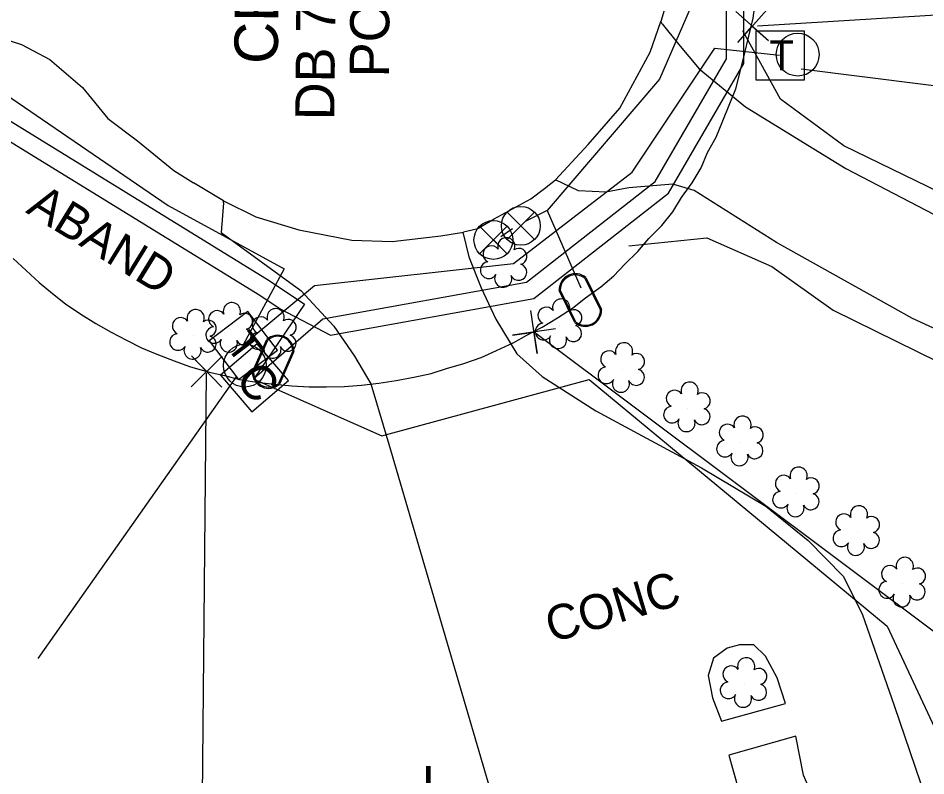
# Model space of a CAD drawing. Extents: x 3040896 to 3051146, y 687568 to 732976.
# Drawn here: x 3049511.5 to 3049615.8, y 693458 to 693545 of the extents above; entities that cross this region are included whole.
import ezdxf

# ---------------------------------------------------------------- set-up
doc = ezdxf.new("R2010")
doc.units = 0
for name, color, linetype in [('Exist Other Culture Area Outline', 7, 'Continuous'), ('Exist Other Culture Fence Line', 7, 'Continuous'), ('Exist Property Corner CELL', 7, 'Continuous'), ('Exist Property Deed Book Text', 7, 'Continuous'), ('Exist Property Line', 7, 'Continuous'), ('Exist Property Owner Text', 7, 'Continuous'), ('Exist Roads Change in Surface', 7, 'Continuous'), ('Exist Roads EOP', 7, 'Continuous'), ('Exist Roads EOP Other', 7, 'Continuous'), ('Exist Roads EOP Other Text', 7, 'Continuous'), ('Exist Utilities Other Pole CELL', 7, 'Continuous'), ('Exist Utilities Power UG Cable SUE', 7, 'Continuous'), ('Exist Utilities Telephone Pedestal CELL', 7, 'Continuous'), ('Exist Utilities Telephone UG Cable', 7, 'Continuous'), ('Exist Utilities TV Pedestal CELL', 7, 'Continuous'), ('Exist Utilities TV UG Cable', 7, 'Continuous'), ('Exist Utilities TV UG Cable Text', 7, 'Continuous'), ('Exist Utilities Water Meter CELL', 7, 'Continuous'), ('Exist Utilities Water UG Line SUE', 7, 'Continuous'), ('Exist Utilities Water Valve CELL', 7, 'Continuous'), ('Exist Vegetation Shrub CELL', 7, 'Continuous'), ('Old_Level_13', 7, 'Continuous')]:
    doc.layers.add(name, color=color, linetype=linetype)

msp = doc.modelspace()

# ---------------------------------------------------------------- linework, layer by layer
at = {"layer": 'Exist Other Culture Area Outline'}
msp.add_lwpolyline([(3049606.13, 693446.67), (3049605.5, 693449.25), (3049601.71, 693458.05), (3049600.82, 693462.53), (3049593.13, 693460.32), (3049594.43, 693455.69), (3049598, 693445.44), (3049596.79, 693445.21), (3049590.63, 693444.06), (3049591.54, 693440.53)], dxfattribs=at)
at = {"layer": 'Exist Other Culture Fence Line'}
for points in [[(3049688.71, 693507.5), (3049665.11, 693510.26), (3049652.25, 693512.77), (3049642.1, 693515.21), (3049629.34, 693520.17), (3049617.37, 693524.98), (3049606.36, 693530.33), (3049599.08, 693535.69), (3049594.75, 693543.54)], [(3049581.65, 693518.83), (3049590.62, 693519.75), (3049598.07, 693516.46), (3049605.11, 693511.44), (3049619.6, 693504.33), (3049633.56, 693498.98), (3049638.36, 693496.65), (3049639.87, 693495.38), (3049641.27, 693491.17), (3049641.15, 693483.27), (3049641.51, 693474.72), (3049641.62, 693467.01), (3049646.7, 693461.24), (3049648.89, 693460), (3049661.5, 693459.17), (3049687.98, 693458.81)]]:
    msp.add_lwpolyline(points, dxfattribs=at)
at = {"layer": 'Exist Property Corner CELL'}
for p, q in [((3049595.83, 693544.09), (3049595.83, 693544.09)), ((3049570.76, 693508.94), (3049570.76, 693508.94)), ((3049533.17, 693504.4), (3049533.17, 693504.4))]:
    msp.add_line(p, q, dxfattribs=at)
for points in [[(3049597.49, 693545.96), (3049594.18, 693542.22), (3049595.83, 693544.09), (3049597.71, 693542.44), (3049593.96, 693545.75)], [(3049573.24, 693509.29), (3049568.29, 693508.58), (3049570.76, 693508.94), (3049571.12, 693506.46), (3049570.41, 693511.41)], [(3049534.92, 693502.62), (3049531.42, 693506.19), (3049533.17, 693504.4), (3049531.39, 693502.65), (3049534.96, 693506.15)]]:
    msp.add_lwpolyline(points, dxfattribs=at)
at = {"layer": 'Exist Property Line'}
for p, q in [((3049596.45, 693544.13), (3049837.98, 693559.07)), ((3049758.19, 693368.58), (3049570.83, 693508.88)), ((3049531.76, 693358.24), (3049533.17, 693504.23))]:
    msp.add_line(p, q, dxfattribs=at)
at = {"layer": 'Exist Roads Change in Surface'}
for points in [[(3049573.25, 693526.41), (3049576.97, 693530.49), (3049580.61, 693534.66), (3049584.09, 693541.1), (3049585.34, 693544.6)], [(3049535.12, 693524.02), (3049538.83, 693522.16), (3049543.74, 693520.67), (3049549.85, 693519.51), (3049554.46, 693519.34), (3049560.07, 693520), (3049562.67, 693520.41)]]:
    msp.add_lwpolyline(points, dxfattribs=at)
at = {"layer": 'Exist Roads EOP'}
for points in [[(3049586.59, 693548.81), (3049585.34, 693544.6)], [(3049479.18, 693542.94), (3049500.69, 693543.36), (3049508.63, 693543), (3049511.9, 693541.98), (3049515.14, 693540.26), (3049518.92, 693537.04), (3049521.8, 693533.46), (3049525.22, 693530.91), (3049529.39, 693527.48), (3049531.65, 693526.08)], [(3049535.12, 693524.02), (3049531.65, 693526.08)], [(3049571.98, 693525.44), (3049573.25, 693526.41)], [(3049564.16, 693520.74), (3049566.2, 693521.93), (3049570.42, 693524.26), (3049571.98, 693525.44)], [(3049564.16, 693520.74), (3049562.67, 693520.41)]]:
    msp.add_lwpolyline(points, dxfattribs=at)
at = {"layer": 'Exist Roads EOP Other'}
for points in [[(3049585.47, 693544.36), (3049585.34, 693544.6)], [(3049585.47, 693544.36), (3049587.36, 693542.01), (3049589.75, 693539.17), (3049595.04, 693534.8), (3049606.59, 693527.73), (3049619.45, 693521.01), (3049629.22, 693516.68), (3049643.55, 693511.19), (3049655.2, 693508.32), (3049669.92, 693506), (3049688.66, 693504.22)], [(3049688.04, 693462.96), (3049645.19, 693463.89), (3049644.71, 693484.03), (3049645, 693490.85), (3049644.66, 693492.55), (3049643.73, 693494.68), (3049642.76, 693496.76), (3049640.6, 693499.11), (3049636.02, 693501.67), (3049625.21, 693505.44), (3049614.23, 693510.48), (3049598.6, 693519.22), (3049589.16, 693525.19), (3049586.73, 693525.91), (3049581.67, 693525.5), (3049579.01, 693524.99), (3049575.89, 693525.17), (3049573.25, 693526.41)], [(3049573.25, 693526.41), (3049573.25, 693526.41)], [(3049535.11, 693523.8), (3049534.83, 693520.39), (3049543.99, 693513.7), (3049547.76, 693509.62), (3049550.14, 693506.16), (3049552.01, 693503), (3049554.08, 693496.07), (3049568.51, 693446.8), (3049572.9, 693447.95), (3049574.06, 693442.53), (3049580.23, 693444.31), (3049582.15, 693437.6)], [(3049535.11, 693523.8), (3049535.12, 693524.02)], [(3049562.62, 693520.26), (3049562.67, 693520.41)], [(3049562.62, 693520.26), (3049563.28, 693517.57), (3049564.68, 693514.02), (3049566.38, 693510.42), (3049568.81, 693506.42), (3049571.71, 693503.85), (3049577.88, 693499.9), (3049590.01, 693493.34), (3049597.39, 693488.95), (3049602.27, 693484.99), (3049606.28, 693480.91), (3049608.47, 693476.55), (3049612.14, 693466.02), (3049618.75, 693446.58), (3049607.87, 693443.4)], [(3049592.29, 693464.24), (3049599.67, 693466.25), (3049598.71, 693469.22), (3049597.34, 693471.69), (3049596.01, 693472.99), (3049594.37, 693472.99), (3049592.94, 693472.62), (3049591.38, 693471.49), (3049590.76, 693469.48), (3049591.25, 693466.9), (3049592.29, 693464.24)]]:
    msp.add_lwpolyline(points, dxfattribs=at)
at = {"layer": 'Exist Utilities Other Pole CELL'}
for centre in [(3049601.05, 693540.81), (3049537.56, 693505.08)]:
    msp.add_circle(centre, 2.46, dxfattribs=at)
at = {"layer": 'Exist Utilities Power UG Cable SUE'}
msp.add_line((3049513.83, 693471.45), (3049536.58, 693503.81), dxfattribs=at)
for points in [[(3049601.44, 693539.19), (3049643.47, 693533.9), (3049686.11, 693541.25), (3049709.32, 693534.5), (3049719.87, 693519.03)], [(3049538.51, 693503.56), (3049553.28, 693497), (3049577.12, 693503.48), (3049611.31, 693475.15), (3049619.76, 693457.12)]]:
    msp.add_lwpolyline(points, dxfattribs=at)
at = {"layer": 'Exist Utilities Telephone Pedestal CELL'}
for p, q in [((3049598.95, 693540.73), (3049598.95, 693540.73)), ((3049537.35, 693507.46), (3049537.35, 693507.46))]:
    msp.add_line(p, q, dxfattribs=at)
for points in [[(3049596.23, 693537.91), (3049601.82, 693537.91), (3049601.82, 693543.5), (3049596.23, 693543.5), (3049596.23, 693537.91)], [(3049533.45, 693507.92), (3049536.83, 693503.47), (3049541.29, 693506.86), (3049537.9, 693511.31), (3049533.45, 693507.92)]]:
    msp.add_lwpolyline(points, dxfattribs=at)
at = {"layer": 'Exist Utilities Telephone UG Cable'}
msp.add_lwpolyline([(3049370.49, 693463.44), (3049372.77, 693468.32), (3049414.62, 693467.37), (3049416.52, 693536.49), (3049507.84, 693537.75), (3049528.76, 693523.49), (3049542.08, 693516.19), (3049537.35, 693507.46), (3049545.57, 693514.29), (3049568.4, 693516.83), (3049582.03, 693527.29), (3049591.54, 693541.56), (3049598.95, 693540.73)], dxfattribs=at)
at = {"layer": 'Exist Utilities TV Pedestal CELL'}
msp.add_line((3049538.66, 693503.68), (3049538.66, 693503.68), dxfattribs=at)
msp.add_lwpolyline([(3049534.75, 693503.99), (3049538.36, 693499.77), (3049542.58, 693503.38), (3049538.97, 693507.6), (3049534.75, 693503.99)], dxfattribs=at)
at = {"layer": 'Exist Utilities TV UG Cable'}
for points in [[(3049372.31, 693460.73), (3049412.78, 693460.14), (3049417.95, 693465.39), (3049419.86, 693533.56), (3049507.37, 693535.14), (3049540.34, 693514.85), (3049544.39, 693512.14), (3049538.66, 693503.68), (3049546.51, 693510.45), (3049569.9, 693514.68), (3049584.7, 693526.23), (3049592.87, 693540.32), (3049592.87, 693551.03), (3049588.22, 693572.59), (3049586.34, 693576.38), (3049592.82, 693579.38)], [(3049372.31, 693460.73), (3049375.54, 693458.68), (3049413.6, 693458.13), (3049419.93, 693464.55), (3049421.8, 693531.59), (3049506.82, 693533.13), (3049539.26, 693513.17), (3049541.61, 693511.6), (3049547.4, 693508.58), (3049570.74, 693512.8), (3049586.23, 693524.89), (3049594.87, 693539.79), (3049594.87, 693551.25), (3049590.12, 693573.26), (3049589.05, 693575.43), (3049592.82, 693579.38)]]:
    msp.add_lwpolyline(points, dxfattribs=at)
at = {"layer": 'Exist Utilities Water Meter CELL'}
for p, q in [((3049576.1, 693512.61), (3049576.1, 693512.61)), ((3049540.81, 693505.53), (3049540.81, 693505.53))]:
    msp.add_line(p, q, dxfattribs=at)
for points in [[(3049576.6, 693515.13), (3049578.39, 693511.47)], [(3049576.73, 693515.19), (3049578.52, 693511.53)], [(3049575.46, 693510.03), (3049573.66, 693513.72)], [(3049575.59, 693510.09), (3049573.79, 693513.78)], [(3049538.43, 693504.35), (3049540.07, 693508.08)], [(3049538.56, 693504.29), (3049540.2, 693508.02)], [(3049543.06, 693506.76), (3049541.41, 693503.01)], [(3049543.18, 693506.71), (3049541.53, 693502.96)]]:
    msp.add_lwpolyline(points, dxfattribs=at)
for centre, radius, start, end in [((3049575.52, 693513.78), 1.86, 49.2315, 182.0329), ((3049575.52, 693513.77), 1.73, 51.3544, 179.8359), ((3049576.66, 693511.45), 1.86, 229.7018, 2.3619), ((3049576.67, 693511.44), 1.73, 231.1807, 0.9263), ((3049541.33, 693506.71), 1.86, 359.9233, 132.5833), ((3049541.33, 693506.72), 1.73, 1.4021, 131.1478), ((3049540.29, 693504.33), 1.86, 179.453, 312.2544), ((3049540.29, 693504.34), 1.73, 181.5759, 310.0573)]:
    msp.add_arc(centre, radius, start, end, dxfattribs=at)
at = {"layer": 'Exist Utilities Water UG Line SUE'}
for p, q in [((3049572.28, 693522.9), (3049569.82, 693521.68)), ((3049568.29, 693520.8), (3049566.96, 693519.89))]:
    msp.add_line(p, q, dxfattribs=at)
msp.add_lwpolyline([(3049589.68, 693548.46), (3049585.19, 693537.99), (3049572.28, 693522.9), (3049576.14, 693514.01)], dxfattribs=at)
at = {"layer": 'Exist Utilities Water Valve CELL'}
for points in [[(3049570.83, 693522.72), (3049567.68, 693519.57), (3049569.25, 693521.14), (3049570.83, 693519.57), (3049567.68, 693522.72)], [(3049567.67, 693521.09), (3049564.52, 693517.94), (3049566.1, 693519.52), (3049567.67, 693517.94), (3049564.52, 693521.09)]]:
    msp.add_lwpolyline(points, dxfattribs=at)
for centre in [(3049569.25, 693521.14), (3049566.1, 693519.52)]:
    msp.add_circle(centre, 2.23, dxfattribs=at)
at = {"layer": 'Exist Vegetation Shrub CELL'}
for p, q in [((3049567.36, 693516.75), (3049567.36, 693516.75)), ((3049535.84, 693509.3), (3049535.84, 693509.3)), ((3049573.66, 693509.71), (3049573.66, 693509.71)), ((3049531.68, 693508.5), (3049531.68, 693508.5)), ((3049540.86, 693508.6), (3049540.86, 693508.6)), ((3049580.88, 693504.68), (3049580.88, 693504.68)), ((3049588.41, 693500.16), (3049588.41, 693500.16)), ((3049594.5, 693496.25), (3049594.5, 693496.25)), ((3049600.93, 693490.39), (3049600.93, 693490.39)), ((3049607.87, 693485.95), (3049607.87, 693485.95)), ((3049613.12, 693480.03), (3049613.12, 693480.03)), ((3049594.91, 693468.5), (3049594.91, 693468.5))]:
    msp.add_line(p, q, dxfattribs=at)
for centre, radius, start, end in [((3049567.59, 693518.79), 0.99, 334.8391, 200.4717), ((3049565.88, 693517.88), 0.968, 35.8908, 245.4216), ((3049569.03, 693517.62), 0.929, 284.4567, 126.0861), ((3049565.56, 693516.05), 0.955, 95.1099, 327.9534), ((3049569, 693515.82), 0.937, 204.9913, 73.4601), ((3049567.23, 693515.07), 0.984, 151.2797, 21.387), ((3049536.07, 693511.34), 0.99, 334.8391, 200.4717), ((3049573.89, 693511.75), 0.99, 334.8391, 200.4717), ((3049531.91, 693510.54), 0.99, 334.8391, 200.4717), ((3049534.36, 693510.43), 0.968, 35.8908, 245.4216), ((3049537.52, 693510.17), 0.929, 284.4567, 126.0861), ((3049541.09, 693510.64), 0.99, 334.8391, 200.4717), ((3049572.18, 693510.83), 0.968, 35.8908, 245.4216), ((3049575.33, 693510.58), 0.929, 284.4567, 126.0861), ((3049530.2, 693509.63), 0.968, 35.8908, 245.4216), ((3049533.35, 693509.37), 0.929, 284.4567, 126.0861), ((3049539.38, 693509.73), 0.968, 35.8908, 245.4216), ((3049542.53, 693509.47), 0.929, 284.4567, 126.0861), ((3049571.86, 693509), 0.955, 95.1099, 327.9534), ((3049534.04, 693508.6), 0.955, 95.1099, 327.9534), ((3049537.48, 693508.37), 0.937, 204.9913, 73.4601), ((3049539.06, 693507.9), 0.955, 95.1099, 327.9534), ((3049575.3, 693508.78), 0.937, 204.9913, 73.4601), ((3049529.88, 693507.8), 0.955, 95.1099, 327.9534), ((3049533.32, 693507.57), 0.937, 204.9913, 73.4601), ((3049535.71, 693507.62), 0.984, 151.2797, 21.387), ((3049542.5, 693507.67), 0.937, 204.9913, 73.4601), ((3049573.53, 693508.02), 0.984, 151.2797, 21.387), ((3049531.55, 693506.82), 0.984, 151.2797, 21.387), ((3049540.73, 693506.92), 0.984, 151.2797, 21.387), ((3049579.39, 693505.81), 0.968, 35.8908, 245.4216), ((3049581.11, 693506.72), 0.99, 334.8391, 200.4717), ((3049582.55, 693505.55), 0.929, 284.4567, 126.0861), ((3049579.08, 693503.97), 0.955, 95.1099, 327.9534), ((3049582.51, 693503.75), 0.937, 204.9913, 73.4601), ((3049580.75, 693503), 0.984, 151.2797, 21.387), ((3049588.64, 693502.2), 0.99, 334.8391, 200.4717), ((3049586.93, 693501.29), 0.968, 35.8908, 245.4216), ((3049590.08, 693501.03), 0.929, 284.4567, 126.0861), ((3049586.61, 693499.46), 0.955, 95.1099, 327.9534), ((3049590.05, 693499.23), 0.937, 204.9913, 73.4601), ((3049588.28, 693498.48), 0.984, 151.2797, 21.387), ((3049594.72, 693498.29), 0.99, 334.8391, 200.4717), ((3049593.01, 693497.38), 0.968, 35.8908, 245.4216), ((3049596.17, 693497.12), 0.929, 284.4567, 126.0861), ((3049592.7, 693495.54), 0.955, 95.1099, 327.9534), ((3049596.13, 693495.32), 0.937, 204.9913, 73.4601), ((3049594.37, 693494.57), 0.984, 151.2797, 21.387), ((3049601.16, 693492.43), 0.99, 334.8391, 200.4717), ((3049599.45, 693491.52), 0.968, 35.8908, 245.4216), ((3049602.6, 693491.26), 0.929, 284.4567, 126.0861), ((3049599.13, 693489.69), 0.955, 95.1099, 327.9534), ((3049602.57, 693489.46), 0.937, 204.9913, 73.4601), ((3049600.8, 693488.71), 0.984, 151.2797, 21.387), ((3049606.38, 693487.08), 0.968, 35.8908, 245.4216), ((3049608.09, 693487.99), 0.99, 334.8391, 200.4717), ((3049609.54, 693486.82), 0.929, 284.4567, 126.0861), ((3049606.07, 693485.25), 0.955, 95.1099, 327.9534), ((3049609.5, 693485.02), 0.937, 204.9913, 73.4601), ((3049607.74, 693484.27), 0.984, 151.2797, 21.387), ((3049613.35, 693482.07), 0.99, 334.8391, 200.4717), ((3049611.64, 693481.15), 0.968, 35.8908, 245.4216), ((3049614.8, 693480.9), 0.929, 284.4567, 126.0861), ((3049611.32, 693479.32), 0.955, 95.1099, 327.9534), ((3049614.76, 693479.1), 0.937, 204.9913, 73.4601), ((3049613, 693478.34), 0.984, 151.2797, 21.387), ((3049595.14, 693470.54), 0.99, 334.8391, 200.4717), ((3049593.43, 693469.62), 0.968, 35.8908, 245.4216), ((3049596.58, 693469.37), 0.929, 284.4567, 126.0861), ((3049593.11, 693467.79), 0.955, 95.1099, 327.9534), ((3049596.55, 693467.57), 0.937, 204.9913, 73.4601), ((3049594.78, 693466.81), 0.984, 151.2797, 21.387)]:
    msp.add_arc(centre, radius, start, end, dxfattribs=at)
at = {"layer": 'Old_Level_13'}
for points in [[(3049594.95, 693540.88), (3049595.95, 693545), (3049596.2, 693547), (3049596.45, 693549), (3049596.45, 693551), (3049596.45, 693553), (3049596.45, 693555), (3049596.45, 693556.94), (3049596.2, 693558.94), (3049595.95, 693560.94), (3049595.45, 693562.88), (3049595.2, 693564.88), (3049594.7, 693566.82), (3049593.95, 693568.69), (3049593.2, 693570.57), (3049592.7, 693572.44), (3049591.7, 693574.25), (3049590.95, 693576.07), (3049589.95, 693577.82), (3049589.2, 693578.82)], [(3049594.95, 693540.88), (3049595.95, 693545), (3049596.2, 693547), (3049596.45, 693549), (3049596.45, 693551), (3049596.45, 693553), (3049596.45, 693555), (3049596.45, 693556.94), (3049596.2, 693558.94), (3049595.95, 693560.94), (3049595.45, 693562.88), (3049595.2, 693564.88), (3049594.7, 693566.82), (3049593.95, 693568.69), (3049593.2, 693570.57), (3049592.7, 693572.44), (3049591.7, 693574.25), (3049590.95, 693576.07), (3049589.95, 693577.82), (3049589.2, 693578.82)], [(3049568.45, 693507.75), (3049569.95, 693508.57), (3049571.7, 693509.5), (3049573.45, 693510.57), (3049575.2, 693511.69), (3049576.7, 693512.88), (3049578.45, 693514.13), (3049579.95, 693515.38), (3049581.2, 693516.75), (3049582.7, 693518.19), (3049583.95, 693519.69), (3049585.45, 693521.19), (3049586.7, 693522.75), (3049587.7, 693524.38), (3049588.95, 693526.07), (3049589.95, 693527.82), (3049590.7, 693529.57), (3049591.7, 693531.32), (3049592.45, 693533.19), (3049593.2, 693535), (3049593.95, 693536.88), (3049594.45, 693538.82), (3049594.95, 693540.88)], [(3049568.45, 693507.75), (3049569.95, 693508.57), (3049571.7, 693509.5), (3049573.45, 693510.57), (3049575.2, 693511.69), (3049576.7, 693512.88), (3049578.45, 693514.13), (3049579.95, 693515.38), (3049581.2, 693516.75), (3049582.7, 693518.19), (3049583.95, 693519.69), (3049585.45, 693521.19), (3049586.7, 693522.75), (3049587.7, 693524.38), (3049588.95, 693526.07), (3049589.95, 693527.82), (3049590.7, 693529.57), (3049591.7, 693531.32), (3049592.45, 693533.19), (3049593.2, 693535), (3049593.95, 693536.88), (3049594.45, 693538.82), (3049594.95, 693540.88)], [(3049510.95, 693517.38), (3049512.45, 693516), (3049513.95, 693514.63), (3049515.45, 693513.38), (3049516.95, 693512.19), (3049518.7, 693511), (3049520.45, 693509.94), (3049522.2, 693508.94), (3049523.95, 693508), (3049525.7, 693507.13), (3049527.45, 693506.38), (3049529.45, 693505.63), (3049531.2, 693505), (3049533.45, 693504.32)], [(3049510.95, 693517.38), (3049512.45, 693516), (3049513.95, 693514.63), (3049515.45, 693513.38), (3049516.95, 693512.19), (3049518.7, 693511), (3049520.45, 693509.94), (3049522.2, 693508.94), (3049523.95, 693508), (3049525.7, 693507.13), (3049527.45, 693506.38), (3049529.45, 693505.63), (3049531.2, 693505), (3049533.45, 693504.32)], [(3049533.45, 693504.32), (3049535.2, 693503.94), (3049536.95, 693503.5), (3049538.95, 693503.19), (3049540.95, 693502.94), (3049542.95, 693502.75), (3049544.95, 693502.63), (3049546.95, 693502.63), (3049548.95, 693502.69), (3049550.95, 693502.82), (3049552.95, 693503.07), (3049554.95, 693503.38), (3049556.95, 693503.75), (3049558.95, 693504.19), (3049560.7, 693504.75), (3049562.7, 693505.32), (3049564.7, 693506), (3049566.45, 693506.82), (3049568.45, 693507.75)], [(3049533.45, 693504.32), (3049535.2, 693503.94), (3049536.95, 693503.5), (3049538.95, 693503.19), (3049540.95, 693502.94), (3049542.95, 693502.75), (3049544.95, 693502.63), (3049546.95, 693502.63), (3049548.95, 693502.69), (3049550.95, 693502.82), (3049552.95, 693503.07), (3049554.95, 693503.38), (3049556.95, 693503.75), (3049558.95, 693504.19), (3049560.7, 693504.75), (3049562.7, 693505.32), (3049564.7, 693506), (3049566.45, 693506.82), (3049568.45, 693507.75)]]:
    msp.add_lwpolyline(points, dxfattribs=at)

# ---------------------------------------------------------------- texts
at = {"layer": 'Exist Property Deed Book Text'}
for s, p in [('PC C SL 124C', (3049554.09, 693538.18)), ('DB 704 PG 665', (3049547.83, 693533.25))]:
    msp.add_text(s, height=4.5004, rotation=89.4292, dxfattribs=at).set_placement(p)
at = {"layer": 'Exist Property Owner Text'}
for s, height, p in [('CEMETERY', 5, (3049541.34, 693539.72)), ('MARJORIE E. POWELL', 5.0005, (3049558.24, 693386.86))]:
    msp.add_text(s, height=height, rotation=89.4638, dxfattribs=at).set_placement(p)
at = {"layer": 'Exist Roads EOP Other Text'}
msp.add_text('CONC', height=4, rotation=16.5918, dxfattribs=at).set_placement((3049572.8, 693473.22))
at = {"layer": 'Exist Utilities Telephone Pedestal CELL'}
msp.add_text('T', height=3.42, dxfattribs=at).set_placement((3049597.82, 693539.02))
msp.add_text('T', height=3.42, rotation=307.2782, dxfattribs=at).set_placement((3049535.3, 693507.32))
at = {"layer": 'Exist Utilities TV Pedestal CELL'}
msp.add_text('C', height=4, rotation=310.5251, dxfattribs=at).set_placement((3049536.29, 693503.38))
at = {"layer": 'Exist Utilities TV UG Cable Text'}
msp.add_text('ABAND', height=4, rotation=328.3925, dxfattribs=at).set_placement((3049512.29, 693522.72))

doc.saveas('drawing.dxf')
